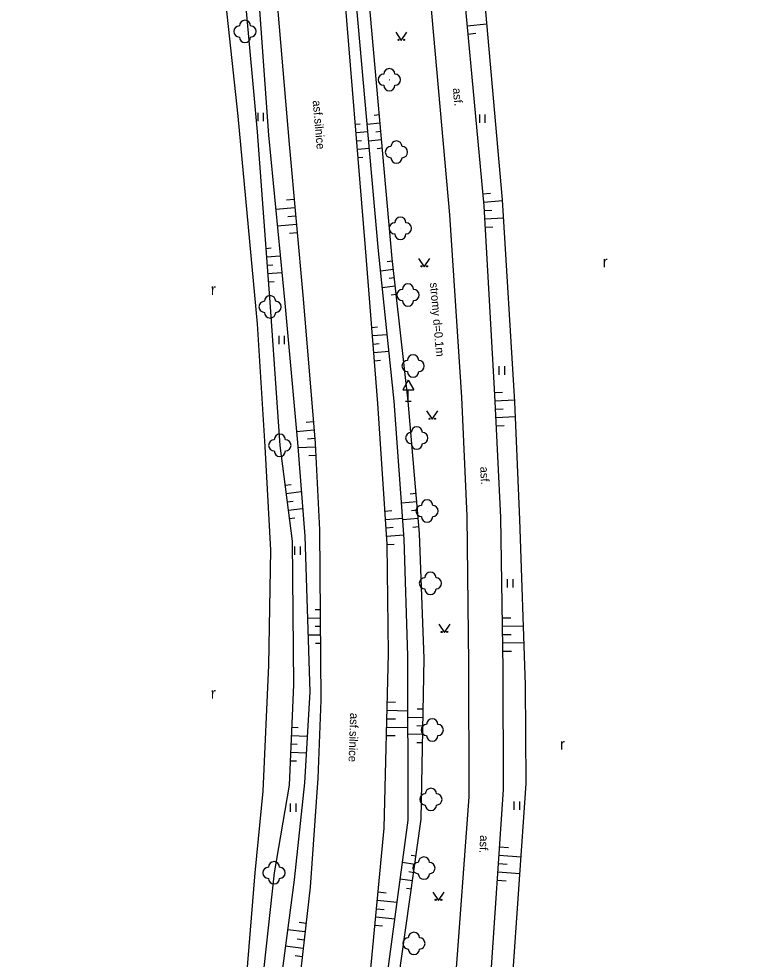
# Model space of a CAD drawing. Extents: x -545714 to -543531, y -1196215 to -1194297.
# Drawn here: x -543649.7 to -543585.1, y -1196035 to -1195950.8 of the extents above; entities that cross this region are included whole.
import ezdxf

# ---------------------------------------------------------------- set-up
doc = ezdxf.new("R2010")
doc.units = 0
for name, color, linetype in [('POMOC_POPIS', 7, 'Continuous'), ('ROZHRANÍ_PLOCH', 7, 'Continuous'), ('VÝŠKOPIS', 7, 'Continuous'), ('ZELEŇ', 7, 'Continuous'), ('ZN_DOPLŇKOVÉ', 7, 'Continuous'), ('ZN_KULTUR', 7, 'Continuous')]:
    doc.layers.add(name, color=color, linetype=linetype)

msp = doc.modelspace()

# ---------------------------------------------------------------- linework, layer by layer
at = {"layer": 'ROZHRANÍ_PLOCH'}
for points in [[(-543607.43, -1196037.02), (-543606.28, -1196019.77), (-543606.3, -1196009), (-543606.5, -1195995.43), (-543607.06, -1195984.44), (-543608.01, -1195967.52), (-543610.49, -1195940.94), (-543612.66, -1195916.66), (-543613.72, -1195904.08), (-543614, -1195894.09), (-543612.96, -1195887.23), (-543612.45, -1195879.29), (-543612.44, -1195876.36), (-543611.47, -1195876.49), (-543610.1, -1195878.26), (-543608.46, -1195876.99), (-543612.9, -1195869.72), (-543613.03, -1195867.25)], [(-543632.41, -1196211.07), (-543630.37, -1196193.32), (-543624.96, -1196151.17), (-543622.81, -1196132.43), (-543618.85, -1196100.43), (-543615.34, -1196072.49), (-543612.05, -1196046.99), (-543610.57, -1196036.97), (-543609.35, -1196020.42), (-543609.38, -1196008.52), (-543609.53, -1195995.3), (-543610, -1195984.65), (-543611.08, -1195968.31), (-543613.38, -1195942.54), (-543615.71, -1195916.87), (-543616.79, -1195903.73), (-543617.14, -1195895.44), (-543615.68, -1195885.08), (-543615.46, -1195880.81), (-543615.86, -1195867.87)], [(-543639.09, -1196203.64), (-543635.02, -1196171.2), (-543630.55, -1196134.22), (-543626.42, -1196101.45), (-543622.95, -1196075.4), (-543619.74, -1196048.22), (-543618.21, -1196036.42), (-543616.96, -1196023.24), (-543616.56, -1196007.59), (-543616.68, -1195997.82), (-543617.53, -1195985.22), (-543618.61, -1195971.27), (-543620.62, -1195946.9), (-543623.05, -1195920.62), (-543624.43, -1195906.58), (-543625.23, -1195895.93), (-543626.15, -1195884.51)], [(-543632.01, -1195889.02), (-543630.66, -1195904.04), (-543629.59, -1195915.71), (-543627.44, -1195938.51), (-543625.46, -1195962.01), (-543624.21, -1195975.84), (-543623.14, -1195988.77), (-543622.74, -1195996.52), (-543622.61, -1196011.77), (-543622.88, -1196018.77), (-543623.58, -1196028.52), (-543624.79, -1196039.27), (-543627.41, -1196061.04), (-543629.27, -1196076.23), (-543632.15, -1196098.41), (-543634.76, -1196118.38), (-543637.1, -1196136.86), (-543638.96, -1196152.81), (-543641.47, -1196173.25), (-543643.67, -1196191.48), (-543644.99, -1196202.76)]]:
    msp.add_lwpolyline(points, dxfattribs=at)
at = {"layer": 'VÝŠKOPIS'}
for points in [[(-543637.68, -1196204.91), (-543633.55, -1196170.77), (-543629.08, -1196133.41), (-543625.09, -1196102.26), (-543621.67, -1196075.01), (-543618.41, -1196048.88), (-543616.7, -1196036.73), (-543614.81, -1196022.52), (-543614.82, -1196007.8), (-543615.15, -1195997.35), (-543616.06, -1195985.01), (-543617.47, -1195971.56), (-543619.73, -1195946.13), (-543622.24, -1195919.83), (-543623.14, -1195907.11), (-543624.18, -1195895.5), (-543625.27, -1195884.41)], [(-543637.05, -1196204.96), (-543632.44, -1196170.19), (-543627.94, -1196133.03), (-543624.22, -1196102.84), (-543620.55, -1196074.64), (-543617.37, -1196049.43), (-543615.66, -1196036.82), (-543613.64, -1196022.43), (-543613.38, -1196008.04), (-543613.8, -1195996.84), (-543614.79, -1195985), (-543616.24, -1195972.22), (-543618.58, -1195945.75), (-543620.93, -1195921.24), (-543621.68, -1195907.9), (-543622.76, -1195895.51), (-543623.49, -1195886.82)], [(-543634.72, -1195888.98), (-543633.71, -1195902.59), (-543632.22, -1195917.58), (-543630.51, -1195936.95), (-543628.32, -1195960.9), (-543627.16, -1195976.56), (-543626.29, -1195988.96), (-543625.18, -1195997.54), (-543625.08, -1196010.41), (-543625.45, -1196019.37), (-543626.81, -1196027.23), (-543628.09, -1196039), (-543629.96, -1196058.78), (-543632.18, -1196076.05), (-543634.6, -1196096.72), (-543637.55, -1196118.36), (-543639.29, -1196135.15), (-543642.06, -1196154.03), (-543643.93, -1196171.42), (-543646.59, -1196191.4), (-543647.93, -1196200.94)], [(-543633.26, -1195889.08), (-543632.32, -1195903.25), (-543630.88, -1195916.7), (-543629.01, -1195937.51), (-543627.31, -1195961.18), (-543625.83, -1195976.22), (-543624.72, -1195988.72), (-543624.05, -1195997.08), (-543623.61, -1196011.03), (-543624.09, -1196019.16), (-543625.02, -1196027.87), (-543626.53, -1196039.42), (-543628.92, -1196059.75), (-543630.9, -1196076.27), (-543633.64, -1196097.53), (-543636.3, -1196118.46), (-543638.55, -1196135.87), (-543640.73, -1196153.47), (-543642.99, -1196172.25), (-543645.26, -1196191.46), (-543646.43, -1196201.58)], [(-543609.51, -1195951.39), (-543607.76, -1195951.23)], [(-543609.45, -1195952.14), (-543608.74, -1195952.07)], [(-543617.38, -1195959.38), (-543617.84, -1195959.42)], [(-543619.52, -1195960.2), (-543619.11, -1195960.17)], [(-543617.31, -1195960.13), (-543618.48, -1195960.23)], [(-543619.46, -1195960.95), (-543618.42, -1195960.86)], [(-543617.18, -1195961.62), (-543618.34, -1195961.73)], [(-543617.24, -1195960.87), (-543617.71, -1195960.92)], [(-543619.4, -1195961.7), (-543618.98, -1195961.66)], [(-543619.34, -1195962.44), (-543618.29, -1195962.36)], [(-543617.11, -1195962.37), (-543617.58, -1195962.41)], [(-543619.28, -1195963.19), (-543618.85, -1195963.16)], [(-543608.11, -1195966.44), (-543607.43, -1195966.38)], [(-543625.01, -1195966.94), (-543625.7, -1195967)], [(-543608.04, -1195967.19), (-543606.35, -1195967.03)], [(-543624.95, -1195967.69), (-543626.65, -1195967.84)], [(-543607.99, -1195967.93), (-543607.31, -1195967.9)], [(-543624.81, -1195969.18), (-543626.51, -1195969.34)], [(-543624.88, -1195968.44), (-543625.56, -1195968.5)], [(-543607.94, -1195968.68), (-543606.25, -1195968.59)], [(-543624.74, -1195969.93), (-543625.42, -1195969.99)], [(-543607.9, -1195969.43), (-543607.23, -1195969.39)], [(-543627.55, -1195971.33), (-543627.06, -1195971.29)], [(-543627.49, -1195972.07), (-543626.25, -1195971.98)], [(-543616.21, -1195972.48), (-543616.67, -1195972.53)], [(-543627.44, -1195972.82), (-543626.93, -1195972.79)], [(-543616.13, -1195973.23), (-543617.28, -1195973.36)], [(-543627.38, -1195973.57), (-543626.1, -1195973.48)], [(-543616.04, -1195973.97), (-543616.51, -1195974.03)], [(-543627.33, -1195974.32), (-543626.81, -1195974.28)], [(-543615.96, -1195974.72), (-543617.13, -1195974.85)], [(-543615.87, -1195975.46), (-543616.34, -1195975.52)], [(-543618.06, -1195978.4), (-543617.54, -1195978.36)], [(-543618, -1195979.14), (-543616.69, -1195979.04)], [(-543617.94, -1195979.89), (-543617.41, -1195979.85)], [(-543617.88, -1195980.64), (-543616.53, -1195980.53)], [(-543617.83, -1195981.39), (-543617.28, -1195981.34)], [(-543607.07, -1195984.23), (-543606.37, -1195984.19)], [(-543607.03, -1195984.98), (-543605.28, -1195984.89)], [(-543606.99, -1195985.73), (-543606.29, -1195985.69)], [(-543623.3, -1195986.86), (-543623.93, -1195986.92)], [(-543606.96, -1195986.48), (-543605.21, -1195986.39)], [(-543623.24, -1195987.61), (-543624.81, -1195987.74)], [(-543606.92, -1195987.22), (-543606.22, -1195987.19)], [(-543623.17, -1195988.36), (-543623.8, -1195988.41)], [(-543623.12, -1195989.11), (-543624.68, -1195989.19)], [(-543623.08, -1195989.86), (-543623.7, -1195989.89)], [(-543625.83, -1195992.53), (-543625.27, -1195992.46)], [(-543625.73, -1195993.28), (-543624.37, -1195993.1)], [(-543614.1, -1195993.28), (-543614.64, -1195993.32)], [(-543625.64, -1195994.02), (-543625.1, -1195993.95)], [(-543614.04, -1195994.03), (-543615.39, -1195994.14)], [(-543625.54, -1195994.77), (-543624.25, -1195994.6)], [(-543616.88, -1195994.84), (-543616.27, -1195994.8)], [(-543613.97, -1195994.77), (-543614.52, -1195994.82)], [(-543625.44, -1195995.51), (-543624.94, -1195995.44)], [(-543616.83, -1195995.59), (-543615.29, -1195995.48)], [(-543613.91, -1195995.52), (-543615.28, -1195995.64)], [(-543616.78, -1195996.33), (-543616.16, -1195996.29)], [(-543616.73, -1195997.08), (-543615.18, -1195996.98)], [(-543613.85, -1195996.27), (-543614.4, -1195996.32)], [(-543616.68, -1195997.83), (-543616.06, -1195997.82)], [(-543622.68, -1196003.69), (-543623.14, -1196003.69)], [(-543622.67, -1196004.44), (-543623.82, -1196004.45)], [(-543606.37, -1196004.4), (-543605.62, -1196004.39)], [(-543622.67, -1196005.19), (-543623.12, -1196005.19)], [(-543606.36, -1196005.15), (-543604.48, -1196005.12)], [(-543622.66, -1196005.94), (-543623.77, -1196005.95)], [(-543606.35, -1196005.9), (-543605.59, -1196005.89)], [(-543622.65, -1196006.69), (-543623.09, -1196006.69)], [(-543606.33, -1196006.65), (-543604.43, -1196006.62)], [(-543606.32, -1196007.4), (-543605.56, -1196007.39)], [(-543616.67, -1196011.93), (-543615.93, -1196011.95)], [(-543616.69, -1196012.68), (-543614.82, -1196012.73)], [(-543613.46, -1196012.59), (-543614, -1196012.58)], [(-543616.71, -1196013.43), (-543615.95, -1196013.45)], [(-543613.48, -1196013.34), (-543614.82, -1196013.31)], [(-543625.24, -1196014.19), (-543624.66, -1196014.21)], [(-543616.73, -1196014.18), (-543614.82, -1196014.23)], [(-543613.49, -1196014.09), (-543614.02, -1196014.08)], [(-543625.27, -1196014.94), (-543623.84, -1196015)], [(-543616.75, -1196014.93), (-543615.97, -1196014.95)], [(-543613.5, -1196014.84), (-543614.82, -1196014.81)], [(-543625.3, -1196015.69), (-543624.73, -1196015.71)], [(-543613.52, -1196015.59), (-543614.04, -1196015.58)], [(-543625.36, -1196017.19), (-543624.81, -1196017.21)], [(-543625.33, -1196016.44), (-543623.93, -1196016.5)], [(-543606.62, -1196024.91), (-543605.83, -1196024.96)], [(-543614.21, -1196026.47), (-543615.32, -1196026.32)], [(-543614.1, -1196025.73), (-543614.55, -1196025.67)], [(-543606.72, -1196026.4), (-543605.93, -1196026.46)], [(-543606.67, -1196025.66), (-543604.7, -1196025.79)], [(-543614.31, -1196027.22), (-543614.75, -1196027.15)], [(-543606.77, -1196027.15), (-543604.8, -1196027.28)], [(-543614.42, -1196027.96), (-543615.51, -1196027.8)], [(-543606.82, -1196027.9), (-543606.04, -1196027.95)], [(-543617.5, -1196028.94), (-543616.78, -1196029.01)], [(-543614.52, -1196028.7), (-543614.96, -1196028.64)], [(-543617.57, -1196029.69), (-543615.79, -1196029.86)], [(-543617.64, -1196030.44), (-543616.94, -1196030.5)], [(-543617.71, -1196031.18), (-543615.98, -1196031.35)], [(-543624.03, -1196032.5), (-543625.6, -1196032.33)], [(-543623.94, -1196031.76), (-543624.57, -1196031.69)], [(-543617.78, -1196031.93), (-543617.1, -1196031.99)], [(-543624.11, -1196033.25), (-543624.75, -1196033.18)], [(-543624.2, -1196033.99), (-543625.8, -1196033.81)], [(-543624.28, -1196034.74), (-543624.93, -1196034.67)]]:
    msp.add_lwpolyline(points, dxfattribs=at)
at = {"layer": 'ZELEŇ'}
for points in [[(-543637.35, -1195889.08), (-543636.25, -1195900.75), (-543634.27, -1195918.95), (-543632.55, -1195936.22), (-543630.06, -1195959.48), (-543628.32, -1195978.08), (-543627.64, -1195989.06), (-543627.13, -1195998.35), (-543627.3, -1196008.65), (-543627.81, -1196019.91), (-543628.52, -1196027.23), (-543629.59, -1196040.43), (-543631.56, -1196057.77), (-543633.61, -1196077.67), (-543635.95, -1196095.36), (-543638.88, -1196118.45), (-543640.59, -1196133.76), (-543643.14, -1196154.34), (-543645.07, -1196170.53), (-543648, -1196190.91), (-543649.65, -1196200.28)], [(-543620.94, -1196214.98), (-543624.31, -1196211.9), (-543626.03, -1196206.25), (-543625.47, -1196195.96), (-543620.17, -1196152.27), (-543617.52, -1196130.8), (-543613.54, -1196101.25), (-543610.23, -1196073.03), (-543606.7, -1196046.58), (-543605.55, -1196038.14), (-543604.25, -1196019.22), (-543604.31, -1196010.39), (-543604.8, -1195995.59), (-543605.27, -1195985.05), (-543606.35, -1195966.98), (-543608.76, -1195939.98), (-543609.96, -1195918.4), (-543608.87, -1195913.01), (-543606.32, -1195907.39), (-543600.46, -1195896.38), (-543598.68, -1195894.64), (-543593.62, -1195901.24), (-543585.09, -1195909.68)]]:
    msp.add_lwpolyline(points, dxfattribs=at)
for centre in [(-543629.41, -1195951.91), (-543616.49, -1195956.23), (-543615.85, -1195962.71), (-543615.5, -1195969.53), (-543614.82, -1195975.5), (-543627.16, -1195976.56), (-543614.36, -1195981.86), (-543614.03, -1195988.3), (-543626.29, -1195988.96), (-543613.11, -1195994.84), (-543612.81, -1196001.31), (-543612.65, -1196014.44), (-543612.77, -1196020.66), (-543626.81, -1196027.23), (-543613.4, -1196026.81), (-543614.29, -1196033.55)]:
    msp.add_circle(centre, 0.0005, dxfattribs=at)
for centre, start, end in [((-543629.91, -1195951.91), 89.99999, 269.99999), ((-543629.41, -1195951.41), 0, 179.99999), ((-543628.91, -1195951.91), 270, 89.99999), ((-543629.41, -1195952.41), 179.99999, 359.99999), ((-543616.99, -1195956.23), 89.99999, 269.99999), ((-543616.49, -1195955.73), 0, 179.99999), ((-543615.99, -1195956.23), 270, 89.99999), ((-543616.49, -1195956.73), 179.99999, 359.99999), ((-543616.35, -1195962.71), 89.99999, 269.99999), ((-543615.85, -1195962.21), 0, 179.99999), ((-543615.35, -1195962.71), 270, 89.99999), ((-543615.85, -1195963.21), 179.99999, 359.99999), ((-543616, -1195969.53), 89.99999, 269.99999), ((-543615.5, -1195969.03), 0, 179.99999), ((-543615, -1195969.53), 270, 89.99999), ((-543615.5, -1195970.03), 179.99999, 359.99999), ((-543615.32, -1195975.5), 89.99999, 269.99999), ((-543614.82, -1195975), 0, 179.99999), ((-543614.32, -1195975.5), 270, 89.99999), ((-543627.16, -1195976.06), 0, 179.99999), ((-543627.66, -1195976.56), 89.99999, 269.99999), ((-543626.66, -1195976.56), 270, 89.99999), ((-543614.82, -1195976), 179.99999, 359.99999), ((-543627.16, -1195977.06), 179.99999, 359.99999), ((-543614.36, -1195981.36), 0, 179.99999), ((-543614.86, -1195981.86), 89.99999, 269.99999), ((-543613.86, -1195981.86), 270, 89.99999), ((-543614.36, -1195982.36), 179.99999, 359.99999), ((-543614.03, -1195987.8), 0, 179.99999), ((-543626.79, -1195988.96), 89.99999, 269.99999), ((-543626.29, -1195988.46), 0, 179.99999), ((-543625.79, -1195988.96), 270, 89.99999), ((-543614.53, -1195988.3), 89.99999, 269.99999), ((-543613.53, -1195988.3), 270, 89.99999), ((-543614.03, -1195988.8), 179.99999, 359.99999), ((-543626.29, -1195989.46), 179.99999, 359.99999), ((-543613.61, -1195994.84), 89.99999, 269.99999), ((-543613.11, -1195994.34), 0, 179.99999), ((-543612.61, -1195994.84), 270, 89.99999), ((-543613.11, -1195995.34), 179.99999, 359.99999), ((-543612.81, -1196000.81), 0, 179.99999), ((-543613.31, -1196001.31), 89.99999, 269.99999), ((-543612.31, -1196001.31), 270, 89.99999), ((-543612.81, -1196001.81), 179.99999, 359.99999), ((-543612.65, -1196013.94), 0, 179.99999), ((-543613.15, -1196014.44), 89.99999, 269.99999), ((-543612.15, -1196014.44), 270, 89.99999), ((-543612.65, -1196014.94), 179.99999, 359.99999), ((-543612.77, -1196020.16), 0, 179.99999), ((-543613.27, -1196020.66), 89.99999, 269.99999), ((-543612.27, -1196020.66), 270, 89.99999), ((-543612.77, -1196021.16), 179.99999, 359.99999), ((-543626.81, -1196026.73), 0, 179.99999), ((-543613.9, -1196026.81), 89.99999, 269.99999), ((-543613.4, -1196026.31), 0, 179.99999), ((-543612.9, -1196026.81), 270, 89.99999), ((-543627.31, -1196027.23), 89.99999, 269.99999), ((-543626.31, -1196027.23), 270, 89.99999), ((-543613.4, -1196027.31), 179.99999, 359.99999), ((-543626.81, -1196027.73), 179.99999, 359.99999), ((-543614.79, -1196033.55), 89.99999, 269.99999), ((-543614.29, -1196033.05), 0, 179.99999), ((-543613.79, -1196033.55), 270, 89.99999), ((-543614.29, -1196034.05), 179.99999, 359.99999)]:
    msp.add_arc(centre, 0.5, start, end, dxfattribs=at)
at = {"layer": 'ZN_DOPLŇKOVÉ'}
for p, q in [((-543614.79, -1195983.134), (-543615.29, -1195984)), ((-543614.79, -1195983.134), (-543614.29, -1195984)), ((-543615.29, -1195984), (-543614.29, -1195984)), ((-543614.79, -1195985), (-543614.79, -1195984)), ((-543615.04, -1195985), (-543614.54, -1195985))]:
    msp.add_line(p, q, dxfattribs=at)
at = {"layer": 'ZN_KULTUR'}
for p, q in [((-543628.24, -1195959.935), (-543628.24, -1195959.185)), ((-543627.74, -1195959.935), (-543627.74, -1195959.185)), ((-543608.4, -1195960.095), (-543608.4, -1195959.345)), ((-543607.9, -1195960.095), (-543607.9, -1195959.345)), ((-543626.36, -1195979.905), (-543626.36, -1195979.155)), ((-543625.86, -1195979.905), (-543625.86, -1195979.155)), ((-543606.65, -1195982.635), (-543606.65, -1195981.885)), ((-543606.15, -1195982.635), (-543606.15, -1195981.885)), ((-543624.94, -1195998.765), (-543624.94, -1195998.015)), ((-543624.44, -1195998.765), (-543624.44, -1195998.015)), ((-543605.91, -1196001.695), (-543605.91, -1196000.945)), ((-543605.41, -1196001.695), (-543605.41, -1196000.945)), ((-543625.34, -1196021.765), (-543625.34, -1196021.015)), ((-543624.84, -1196021.765), (-543624.84, -1196021.015)), ((-543605.31, -1196021.595), (-543605.31, -1196020.845)), ((-543604.81, -1196021.595), (-543604.81, -1196020.845))]:
    msp.add_line(p, q, dxfattribs=at)
for points in [[(-543615.92, -1195951.96), (-543615.42, -1195952.71), (-543614.92, -1195951.96)], [(-543613.87, -1195972.23), (-543613.37, -1195972.98), (-543612.87, -1195972.23)], [(-543613.15, -1195985.88), (-543612.65, -1195986.63), (-543612.15, -1195985.88)], [(-543612.06, -1196004.97), (-543611.56, -1196005.72), (-543611.06, -1196004.97)], [(-543612.59, -1196028.95), (-543612.09, -1196029.7), (-543611.59, -1196028.95)]]:
    msp.add_lwpolyline(points, dxfattribs=at)
for centre in [(-543615.67, -1195952.66), (-543615.17, -1195952.66), (-543613.62, -1195972.93), (-543613.12, -1195972.93), (-543612.9, -1195986.58), (-543612.4, -1195986.58), (-543611.81, -1196005.67), (-543611.31, -1196005.67), (-543612.34, -1196029.65), (-543611.84, -1196029.65)]:
    msp.add_circle(centre, 0.05, dxfattribs=at)

# ---------------------------------------------------------------- texts
at = {"layer": 'POMOC_POPIS'}
for s, rotation, p in [('asf.', 275.10018, (-543610.81, -1195957)), ('asf.silnice', 274.81611, (-543623.35, -1195958.1)), ('asf.', 272.52692, (-543608.36, -1195990.88)), ('asf.silnice', 268.00926, (-543619.99, -1196012.9)), ('asf.', 267.54218, (-543608.36, -1196023.85))]:
    msp.add_text(s, height=0.75, rotation=rotation, dxfattribs=at).set_placement(p)
at = {"layer": 'ZELEŇ'}
msp.add_text('stromy d=0.1m', height=0.75, rotation=274.91088, dxfattribs=at).set_placement((-543612.86, -1195974.41))
at = {"layer": 'ZN_KULTUR'}
for p in [(-543597.398, -1195973.032), (-543632.468, -1195975.502), (-543632.468, -1196011.652), (-543601.218, -1196016.212)]:
    msp.add_text('r', height=1, dxfattribs=at).set_placement(p)

doc.saveas('drawing.dxf')
